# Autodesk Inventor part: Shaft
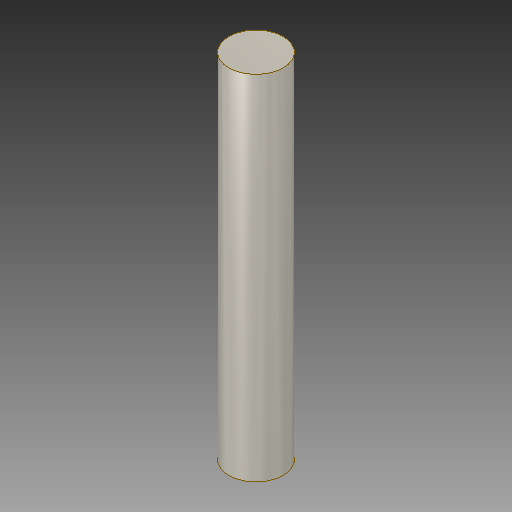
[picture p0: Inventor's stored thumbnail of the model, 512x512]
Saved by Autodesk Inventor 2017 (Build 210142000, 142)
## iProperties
Created: 2020-03
Part Number: Shaft
Material: Titanium
Document SubType Name: Modeling
Designer: user
Density: 4.51 g/cm^3
Appearance: Titanium
Mass: 1.47353 g
Surface Area: 3.51858 cm^2
Volume: 0.326726 cm^3
Author: user
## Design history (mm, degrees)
sketch "Sketch1"
  geometry: C1 r 2 at (0, 0); 1 further point
  constraints: 1 centre point, 1 coincident
  dimensions: "d0" = 4 diameter of C1
extrude "Extrusion1" new body sketch "Sketch1" stored distance "d1" = 26; taper "d2" = 0 deg
body "Solid1"
